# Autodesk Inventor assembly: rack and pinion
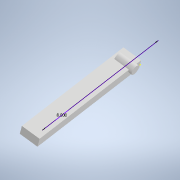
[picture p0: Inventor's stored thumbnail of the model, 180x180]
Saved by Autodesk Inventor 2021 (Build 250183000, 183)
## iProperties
Created: 2021-07
Part Number: rack and pinion
Document SubType Name: Assembly
Designer: adams
Author: adams
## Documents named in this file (3)
- C:\Users\adams\Documents\cannon\cymbals\gear\rack and pinion.iam
- C:\Users\adams\Documents\cannon\cymbals\gear\rack.ipt
- C:\Users\adams\Documents\cannon\cymbals\gear\pinon.ipt
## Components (2 placed, 2 different names)
1. rack:1 — Rotation/Translation:1, Angle:1, Rotation/Translation:2
2. pinon:1 — Rotation/Translation:1, Angle:1, Rotation/Translation:2
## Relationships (3: RelateRotateTranslate 2, Angle 1)
- Rotation/Translation:1 [RelateRotateTranslate]: rack:1 ↔ pinon:1
- Angle:1: rack:1 ↔ pinon:1
- Rotation/Translation:2 [RelateRotateTranslate]: rack:1 ↔ pinon:1
